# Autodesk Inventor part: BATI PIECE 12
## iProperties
Created: 2004-11
Part Number: BATI PIECE 12
Document SubType Name: Modeling
Designer: Bruno
Manufacturer: Standard
Standards Organization: Custom
Author: Bruno
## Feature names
1. Base1
